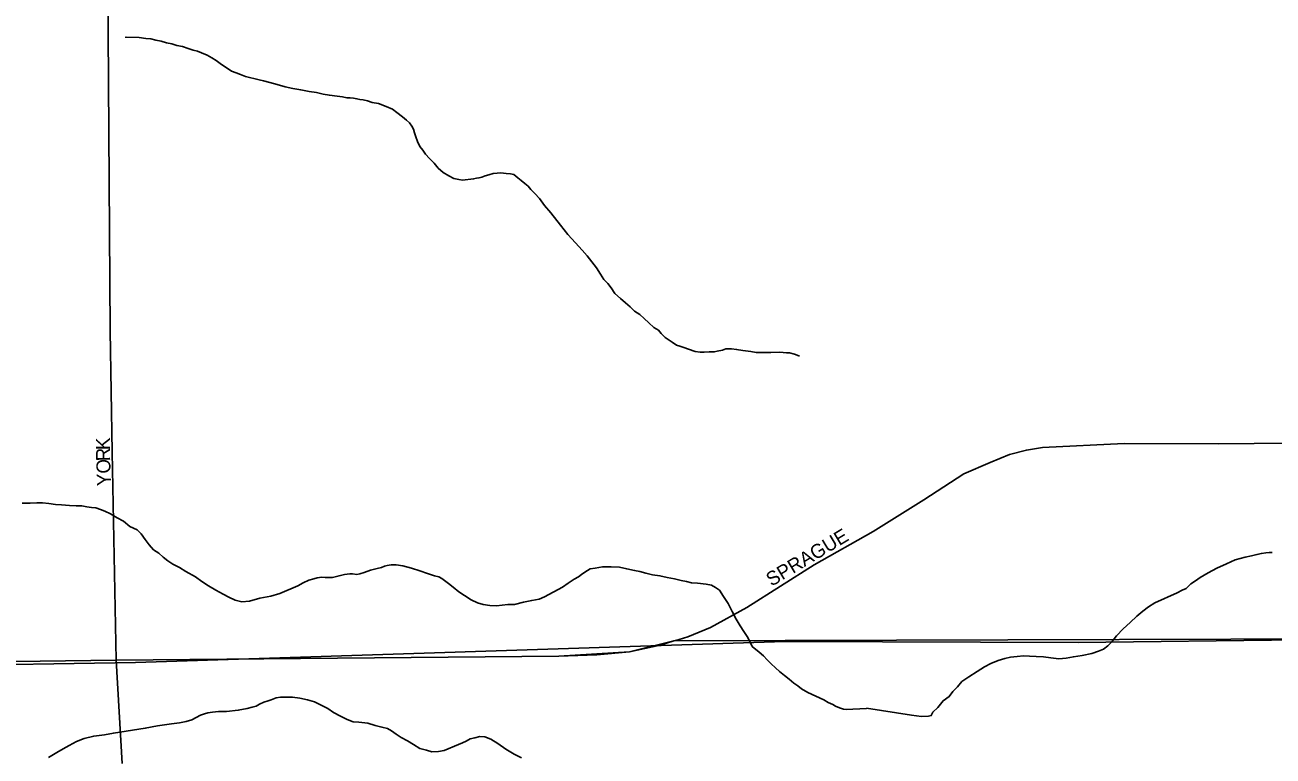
# Model space of a CAD drawing. Extents: x 2010165 to 2382125, y 1060529 to 1407316.
# Drawn here: x 2171530 to 2175988, y 1221171 to 1223780 of the extents above; entities that cross this region are included whole.
import ezdxf

# ---------------------------------------------------------------- set-up
doc = ezdxf.new("R2010")
doc.units = 0
for name, color, linetype in [('GM_X_City_Street', 7, 'Continuous'), ('GM_X_City_Street_Text', 7, 'Continuous'), ('GM_X_Corporation', 7, 'Continuous'), ('GM_X_Minor_River', 7, 'Continuous'), ('GM_X_Section', 7, 'Continuous')]:
    doc.layers.add(name, color=color, linetype=linetype)

msp = doc.modelspace()

# ---------------------------------------------------------------- linework, layer by layer
at = {"layer": 'GM_X_City_Street'}
for points in [[(2171842.3, 1222255.7), (2171834.4, 1222688.7), (2171826.6, 1223933.5), (2171816, 1225067.4)], [(2173867.2, 1221587.4), (2173897.9, 1221596.5), (2173978.7, 1221630.3), (2174108.5, 1221701.2), (2174348.5, 1221852.9), (2174560.1, 1221972.7), (2174740.7, 1222086), (2174884.1, 1222178.1), (2174978, 1222218.8), (2175047.1, 1222247.2), (2175107.3, 1222263.1), (2175164, 1222272), (2175456.1, 1222286.1), (2175794.5, 1222285.7), (2178573.3, 1222312.1)], [(2171855.8, 1221513), (2171842.3, 1222255.7)], [(2171855.8, 1221513), (2173437.5, 1221527.9), (2173572.9, 1221532.4), (2173689.6, 1221543), (2173798.7, 1221567), (2173848.3, 1221581.8), (2173867.2, 1221587.4)], [(2164895.8, 1221436.7), (2167972.5, 1221461.7), (2171855.8, 1221513)], [(2171877.5, 1221144), (2171855.8, 1221513)]]:
    msp.add_lwpolyline(points, dxfattribs=at)
at = {"layer": 'GM_X_Corporation'}
for points in [[(2164832.8, 1218637), (2164895.8, 1221436.7), (2167972.5, 1221461.7), (2171855.8, 1221513), (2173437.5, 1221527.9), (2173689.6, 1221543), (2173848.3, 1221581.8), (2177029.6, 1221591.6), (2178406.5, 1221597), (2181920.6, 1221614.8), (2182220.8, 1221647.5), (2183139.3, 1221656.4), (2185661.2, 1221692.3), (2186878.7, 1221701), (2186923.4, 1220744.1)], [(2188806.8, 1221708.2), (2187206.7, 1221703.9), (2186878.7, 1221701), (2185661.2, 1221692.3), (2183139.3, 1221656.4), (2182220.8, 1221647.5), (2181920.6, 1221614.8), (2178406.5, 1221597), (2177029.6, 1221591.6), (2173848.3, 1221581.8), (2173689.6, 1221543), (2173437.5, 1221527.9), (2171855.8, 1221513), (2167972.5, 1221461.7), (2164895.8, 1221436.7)]]:
    msp.add_lwpolyline(points, dxfattribs=at)
at = {"layer": 'GM_X_Minor_River'}
for points in [[(2171887.8, 1223737.4), (2171937.9, 1223736), (2171891.8, 1223737.4), (2171937.9, 1223736), (2171962, 1223732.3), (2171980, 1223730.5), (2171998.1, 1223726.7), (2172016.2, 1223722.9), (2172036.3, 1223717.2), (2172054.4, 1223713.4), (2172072.5, 1223707.6), (2172092.6, 1223703.8), (2172112.7, 1223696), (2172130.8, 1223690.2), (2172146.9, 1223686.4), (2172161, 1223680.6), (2172181.1, 1223672.8), (2172197.3, 1223662.9), (2172213.4, 1223653.1), (2172227.6, 1223643.2), (2172268, 1223615.6), (2172284.1, 1223609.8), (2172300.2, 1223604), (2172318.4, 1223596.2), (2172332.4, 1223592.4), (2172352.5, 1223588.6), (2172366.6, 1223584.8), (2172382.7, 1223580.9), (2172404.8, 1223575.2), (2172430.9, 1223567.5), (2172459.1, 1223559.8), (2172487.2, 1223554.1), (2172515.3, 1223548.4), (2172545.5, 1223542.8), (2172571.6, 1223539.1), (2172595.7, 1223533.4), (2172617.8, 1223529.6), (2172645.9, 1223526), (2172663.9, 1223524.2), (2172680, 1223520.4), (2172692, 1223520.5), (2172704.1, 1223518.6), (2172716.1, 1223516.8), (2172726.1, 1223514.9), (2172738.2, 1223513.1), (2172754.3, 1223509.2), (2172770.4, 1223503.4), (2172792.5, 1223499.7), (2172820.6, 1223490), (2172842.8, 1223480.2), (2172859, 1223468.4), (2172879.2, 1223452.6), (2172893.4, 1223440.7), (2172903.5, 1223430.8), (2172911.7, 1223418.9), (2172917.9, 1223408.9), (2172922, 1223394.9), (2172926.2, 1223380.9), (2172932.5, 1223364.9), (2172940.7, 1223347), (2172950.9, 1223333.1), (2172961.1, 1223319.1), (2172975.3, 1223303.3), (2172991.6, 1223287.4), (2173005.8, 1223269.5), (2173024.1, 1223253.7), (2173044.3, 1223241.9), (2173062.4, 1223232.1), (2173080.5, 1223228.3), (2173092.6, 1223226.4), (2173132.6, 1223230.9), (2173142.6, 1223233.1), (2173152.5, 1223235.2), (2173162.5, 1223237.3), (2173174.5, 1223241.5), (2173186.5, 1223245.6), (2173202.4, 1223249.9), (2173216.4, 1223252), (2173230.5, 1223252.2), (2173248.5, 1223250.4), (2173264.6, 1223248.6), (2173276.6, 1223246.8), (2173290.8, 1223234.9), (2173302.9, 1223225), (2173315.1, 1223215.1), (2173327.2, 1223205.2), (2173337.4, 1223193.3), (2173351.6, 1223179.4), (2173367.9, 1223161.6), (2173386.2, 1223135.7), (2173408.6, 1223109.9), (2173443.2, 1223066.2), (2173469.7, 1223032.4), (2173496.2, 1223002.6), (2173520.6, 1222976.8), (2173538.8, 1222957), (2173555.1, 1222935.1), (2173571.5, 1222913.3), (2173585.8, 1222891.4), (2173598.1, 1222871.5), (2173612.3, 1222857.6)], [(2173612.3, 1222857.6), (2173624.5, 1222841.7), (2173636.8, 1222821.8), (2173657, 1222804), (2173675.3, 1222788.1), (2173691.5, 1222774.3), (2173707.7, 1222758.4), (2173725.9, 1222746.6), (2173742.1, 1222732.8), (2173758.4, 1222716.9), (2173776.6, 1222701.1), (2173792.7, 1222691.2), (2173802.9, 1222679.3), (2173817.1, 1222665.5), (2173841.4, 1222647.7), (2173857.6, 1222637.9), (2173869.6, 1222634), (2173879.7, 1222630.1), (2173924, 1222614.6), (2173942, 1222612.8), (2173956.1, 1222613), (2173974.1, 1222613.2), (2173992.1, 1222613.4), (2174002.1, 1222615.6), (2174022.1, 1222619.8), (2174034.1, 1222624), (2174054.1, 1222624.2), (2174072.1, 1222622.4), (2174094.2, 1222618.7), (2174122.3, 1222615), (2174142.4, 1222611.3), (2174166.4, 1222611.6), (2174194.5, 1222611.9), (2174226.5, 1222612.3), (2174250.6, 1222610.6), (2174260.6, 1222610.7), (2174278.7, 1222604.9), (2174294.8, 1222599.1), (2174296.8, 1222599.1)], [(2171520.8, 1222073.6), (2171548.8, 1222073.9), (2171572.9, 1222074.2), (2171592.9, 1222074.4), (2171615, 1222072.7), (2171639.1, 1222069), (2171661.1, 1222067.2), (2171689.2, 1222065.6), (2171713.3, 1222063.9), (2171733.3, 1222064.1), (2171751.4, 1222060.3), (2171767.4, 1222058.5), (2171783.5, 1222056.7), (2171799.6, 1222050.9), (2171815.7, 1222045.1), (2171835.9, 1222035.3), (2171860.1, 1222021.5), (2171882.3, 1222009.8), (2171904.6, 1221990), (2171930.8, 1221978.2), (2171945, 1221964.4), (2171959.3, 1221944.5), (2171973.5, 1221924.6), (2171989.8, 1221906.7)], [(2171989.8, 1221906.7), (2172008, 1221894.9), (2172024.2, 1221881.1), (2172040.4, 1221867.2), (2172058.6, 1221855.4), (2172082.8, 1221843.7), (2172105, 1221829.9), (2172139.3, 1221810.2), (2172161.6, 1221794.5), (2172185.8, 1221778.7), (2172212.1, 1221763), (2172238.3, 1221749.2), (2172258.5, 1221737.5), (2172280.7, 1221727.7), (2172304.8, 1221722), (2172332.8, 1221724.3), (2172368.7, 1221734.8), (2172408.7, 1221741.3), (2172440.6, 1221751.7), (2172504.4, 1221778.6), (2172524.3, 1221788.9), (2172544.2, 1221799.1), (2172562.2, 1221803.4), (2172574.1, 1221807.5), (2172590.1, 1221809.7), (2172602.2, 1221807.9), (2172616.2, 1221808), (2172628.2, 1221808.2), (2172652.2, 1221814.5), (2172672.1, 1221818.8), (2172690.2, 1221821), (2172700.2, 1221821.1), (2172716.2, 1221819.3), (2172726.2, 1221821.4), (2172742.2, 1221825.6), (2172764.1, 1221833.9), (2172788.1, 1221840.2), (2172804, 1221844.5), (2172814, 1221848.6), (2172824, 1221850.7), (2172838, 1221852.9), (2172856, 1221853.1), (2172880.1, 1221849.4), (2172910.3, 1221841.8), (2172940.4, 1221832.1), (2172968.6, 1221822.4), (2172992.8, 1221814.7), (2173008.8, 1221810.8), (2173018.9, 1221804.9), (2173043.2, 1221787.2), (2173059.4, 1221773.3), (2173079.7, 1221757.5), (2173099.9, 1221743.7), (2173124.1, 1221728), (2173146.3, 1221718.2), (2173166.4, 1221712.4), (2173190.5, 1221708.7), (2173214.6, 1221707), (2173234.6, 1221709.3), (2173254.6, 1221711.5), (2173268.6, 1221711.7), (2173278.6, 1221711.8), (2173310.5, 1221720.2), (2173340.5, 1221726.6), (2173366.5, 1221730.9), (2173386.4, 1221739.2), (2173450.1, 1221774.1), (2173469.9, 1221788.4), (2173491.8, 1221802.7), (2173507.7, 1221810.9), (2173517.6, 1221819.1), (2173529.5, 1221827.2), (2173549.4, 1221839.5), (2173567.4, 1221841.8), (2173593.4, 1221846.1), (2173623.5, 1221846.4), (2173653.5, 1221844.8), (2173679.7, 1221839.1), (2173707.8, 1221833.4), (2173725.9, 1221829.6), (2173748, 1221823.9), (2173772.1, 1221818.2), (2173798.2, 1221814.5), (2173824.3, 1221808.8), (2173850.4, 1221803.1), (2173874.5, 1221797.4), (2173892.6, 1221793.6), (2173910.7, 1221789.8), (2173932.8, 1221788), (2173962.9, 1221784.4), (2173982.9, 1221780.6), (2173997.1, 1221772.8), (2174011.2, 1221762.9), (2174025.5, 1221741), (2174041.9, 1221715.1), (2174056.3, 1221687.2), (2174070.7, 1221659.3), (2174085, 1221635.4), (2174097.3, 1221615.5), (2174111.6, 1221593.6), (2174128, 1221561.7)], [(2174536, 1221341.6), (2174696.7, 1221317.4), (2174732.9, 1221312.4), (2174757, 1221313), (2174767, 1221315.3), (2174772.6, 1221327.5), (2174790.3, 1221344), (2174809.6, 1221368.6), (2174831.3, 1221383.2), (2174844.8, 1221401.7), (2174860.4, 1221418.1), (2174876, 1221436.6), (2174901.6, 1221453.3), (2174931.2, 1221472.2), (2174956.8, 1221488.9), (2174980.5, 1221501.6), (2175006.3, 1221512.3), (2175030.2, 1221519), (2175050.1, 1221523.5), (2175074.1, 1221526.1), (2175096.1, 1221528.8), (2175118.2, 1221527.3), (2175142.3, 1221525.9), (2175168.4, 1221524.6), (2175194.6, 1221521.3), (2175222.7, 1221518), (2175248.7, 1221520.7), (2175274.7, 1221525.4), (2175306.6, 1221530.3), (2175340.5, 1221537.2), (2175364.3, 1221545.8), (2175382.2, 1221552.3), (2175397.9, 1221564.8), (2175411.6, 1221579.2), (2175429.1, 1221599.8), (2175452.5, 1221624.5), (2175477.9, 1221647.2), (2175501.4, 1221669.9), (2175522.9, 1221688.6), (2175542.6, 1221703.1), (2175566.2, 1221717.8), (2175645.5, 1221754), (2175663.3, 1221762.5), (2175677.2, 1221768.9), (2175694.8, 1221785.4), (2175710.5, 1221795.9), (2175728.2, 1221808.4), (2175755.9, 1221825.2), (2175787.5, 1221842.1), (2175821.2, 1221857), (2175852.9, 1221871.9), (2175888.7, 1221880.9), (2175910.7, 1221885.5), (2175930.6, 1221890), (2175946.5, 1221894.5), (2175962.5, 1221896.9), (2175974.5, 1221897.2), (2175984.5, 1221897.5)], [(2174128, 1221561.7), (2174152.4, 1221541.9), (2174168.6, 1221528.1), (2174180.8, 1221514.2), (2174195, 1221500.3), (2174211.2, 1221486.4), (2174225.4, 1221472.6), (2174243.6, 1221458.8), (2174259.8, 1221444.9), (2174276, 1221431.1), (2174290.2, 1221421.2), (2174304.3, 1221411.3), (2174326.5, 1221397.6), (2174383, 1221372.2), (2174399.1, 1221362.3), (2174415.3, 1221354.5), (2174425.3, 1221348.6), (2174439.5, 1221342.8), (2174453.5, 1221338.9), (2174463.6, 1221337), (2174536, 1221340.2)], [(2171614.8, 1221165.8), (2171644.6, 1221184.2), (2171666.5, 1221196.5), (2171688.4, 1221208.8), (2171714.2, 1221223.2), (2171742.1, 1221233.5), (2171776.1, 1221242), (2171814.1, 1221246.4), (2171846.1, 1221252.9), (2171960, 1221270.3), (2172004, 1221278.9), (2172054, 1221285.5), (2172082, 1221289.9), (2172106, 1221294.2), (2172125.9, 1221300.4), (2172141.9, 1221308.6), (2172157.8, 1221316.9), (2172171.8, 1221321.1), (2172183.7, 1221325.2), (2172199.7, 1221327.4), (2172221.7, 1221329.7), (2172249.8, 1221330), (2172291.8, 1221334.6), (2172323.8, 1221341), (2172341.7, 1221345.2), (2172355.7, 1221349.4), (2172367.7, 1221355.6), (2172383.6, 1221363.8), (2172399.5, 1221368), (2172409.5, 1221372.1), (2172427.5, 1221378.4), (2172443.5, 1221380.6), (2172457.5, 1221380.7), (2172485.5, 1221381.1), (2172511.6, 1221377.4), (2172539.7, 1221371.7), (2172563.9, 1221364), (2172588.1, 1221352.2), (2172612.3, 1221340.5), (2172632.5, 1221326.7), (2172656.7, 1221312.9), (2172680.9, 1221301.2), (2172703, 1221293.4), (2172723.1, 1221291.7), (2172755.2, 1221288.1), (2172781.4, 1221280.4)], [(2172781.4, 1221280.4), (2172805.5, 1221274.6), (2172825.6, 1221268.9), (2172839.7, 1221261), (2172855.9, 1221249.2), (2172874.1, 1221237.3), (2172896.3, 1221225.6), (2172918.5, 1221211.8), (2172940.7, 1221198), (2172964.8, 1221192.3), (2172982.9, 1221186.5), (2173007, 1221186.8), (2173027, 1221191.1), (2173078.8, 1221211.8), (2173092.7, 1221217.9), (2173106.7, 1221224.1), (2173120.6, 1221232.3), (2173136.5, 1221236.5), (2173154.5, 1221240.8), (2173172.6, 1221239), (2173194.7, 1221231.2), (2173219, 1221215.5), (2173247.3, 1221195.8), (2173277.6, 1221178.1), (2173303.8, 1221164.3)]]:
    msp.add_lwpolyline(points, dxfattribs=at)
at = {"layer": 'GM_X_Section'}
msp.add_lwpolyline([(2175291.6, 1221576.6), (2176081.6, 1221585.6), (2176133.3, 1216538.6), (2170517.3, 1216673.9), (2170463.9, 1221481), (2171925.4, 1221504.9), (2174244.4, 1221580)], close=True, dxfattribs=at)

# ---------------------------------------------------------------- texts
at = {"layer": 'GM_X_City_Street_Text'}
for s, rotation, p in [('K', 90.2186, (2171833.8, 1222263.2)), ('R', 91.4813, (2171834.8, 1222223.8)), ('O', 92.0985, (2171836.4, 1222180)), ('Y', 92.0985, (2171838, 1222136)), ('SPRAGUE', 30.9649, (2174196.5, 1221774.8))]:
    msp.add_text(s, height=50, rotation=rotation, dxfattribs=at).set_placement(p)

doc.saveas('drawing.dxf')
